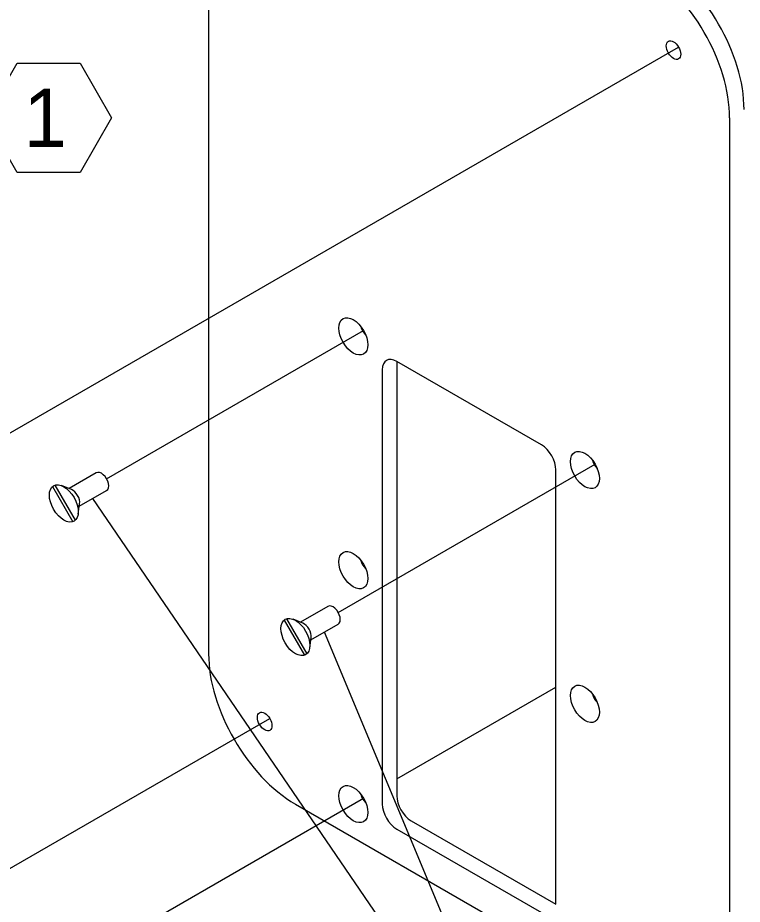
# Model space of a CAD drawing. Extents: x 99862 to 103151, y 100000 to 105076.
# Drawn here: x 100958 to 101157.1, y 103460 to 103703.7 of the extents above; entities that cross this region are included whole.
import ezdxf

# ---------------------------------------------------------------- set-up
doc = ezdxf.new("R2010")
doc.units = 0
for name, color, linetype in [('Level 15', 7, 'Continuous'), ('Level 16', 7, 'Continuous'), ('Level 20', 7, 'Continuous'), ('Level 41', 7, 'Continuous')]:
    doc.layers.add(name, color=color, linetype=linetype)

msp = doc.modelspace()

# ---------------------------------------------------------------- linework, layer by layer
at = {"layer": 'Level 15'}
for q in [(100978.65, 103571.56), (101042.29, 103534.82)]:
    msp.add_line((101102.82, 103389.59), q, dxfattribs=at)
at = {"layer": 'Level 16'}
for p, q in [((100947.75, 103584.89), (101139.59, 103695.65)), ((100982.4, 103576.97), (101053.01, 103617.74)), ((101046.04, 103540.23), (101116.65, 103581)), ((101062.13, 103494.41), (101105.88, 103519.67)), ((100954.54, 103469.03), (101027.26, 103511.02)), ((100982.4, 103448.37), (101053.01, 103489.14))]:
    msp.add_line(p, q, dxfattribs=at)
at = {"layer": 'Level 20'}
msp.add_lwpolyline([(100949.16, 103676.21), (100957.82, 103691.21), (100975.14, 103691.21), (100983.78, 103676.21), (100975.14, 103661.22), (100957.82, 103661.22), (100949.16, 103676.21)], dxfattribs=at)
at = {"layer": 'Level 41'}
for p, q in [((101010.42, 103758.86), (101010.42, 103528.85)), ((101153.61, 103676.19), (101153.61, 103446.18)), ((101062.13, 103609.23), (101062.13, 103489.81)), ((101101.9, 103586.26), (101062.13, 103609.23)), ((101058.15, 103606.93), (101058.15, 103487.52)), ((101105.88, 103459.96), (101105.88, 103579.37)), ((100979.58, 103578.59), (100972.09, 103574.27)), ((100967.53, 103574.84), (100973.12, 103565.16)), ((100968.18, 103575.21), (100973.77, 103565.54)), ((100972.73, 103574.01), (100970.03, 103575.08)), ((100974.9, 103569.39), (100982.4, 103573.72)), ((100974.58, 103567.21), (100975, 103570.08)), ((101043.22, 103541.85), (101035.73, 103537.52)), ((101031.17, 103538.1), (101036.76, 103528.42)), ((101031.82, 103538.47), (101037.41, 103528.79)), ((101036.37, 103537.27), (101033.67, 103538.34)), ((101038.54, 103532.65), (101046.04, 103536.98)), ((101038.22, 103530.47), (101038.64, 103533.33)), ((101034.29, 103487.52), (101129.75, 103432.4)), ((101066.11, 103482.93), (101105.88, 103459.96)), ((101062.13, 103480.63), (101101.9, 103457.66))]:
    msp.add_line(p, q, dxfattribs=at)
for centre, major_axis, start_param, end_param in [((101133.72, 103692.26), (-16.88, 29.23), 3.926991, 5.497787), ((101129.75, 103689.97), (-16.88, 29.23), 3.926991, 5.497787), ((101054.17, 103618.41), (-1.41, 2.44), 1.084101, 2.057491), ((101062.13, 103604.63), (-2.81, 4.87), 5.497787, 7.068583), ((101101.9, 103581.67), (-2.81, 4.87), 3.926991, 5.497787), ((101117.81, 103581.67), (-1.41, 2.44), 1.084101, 2.057491), ((100980.99, 103576.16), (1.41, -2.44), 6.28318, 9.424778), ((100980.99, 103576.16), (1.41, -2.44), 3.141593, 3.141605), ((100973.03, 103571.57), (1.41, -2.44), 0.630137, 2.511455), ((101054.17, 103554.11), (-1.41, 2.44), 1.084101, 2.057491), ((101044.63, 103539.42), (1.41, -2.44), 6.28318, 9.424778), ((101044.63, 103539.42), (1.41, -2.44), 3.141593, 3.141605), ((101036.67, 103534.82), (1.41, -2.44), 0.630137, 2.511453), ((101034.29, 103515.07), (16.88, -29.23), 3.926991, 5.497787), ((101117.81, 103517.37), (-1.41, 2.44), 1.084101, 2.057491), ((101054.17, 103489.81), (-1.41, 2.44), 1.084101, 2.057491), ((101066.11, 103487.52), (-2.81, 4.87), 0.785398, 2.356194), ((101062.13, 103485.22), (-2.81, 4.87), 0.785398, 2.356194)]:
    msp.add_ellipse(centre, major_axis=major_axis, ratio=0.57735, start_param=start_param, end_param=end_param, dxfattribs=at)
for centre, major_axis in [((101138.18, 103694.84), (-1.41, 2.44)), ((101050.2, 103616.12), (-2.81, 4.87)), ((101113.84, 103579.37), (-2.81, 4.87)), ((100970.65, 103570.19), (-2.81, 4.87)), ((101050.2, 103551.82), (-2.81, 4.87)), ((101034.29, 103533.45), (-2.81, 4.87)), ((101113.84, 103515.07), (-2.81, 4.87)), ((101025.85, 103510.2), (-1.41, 2.44)), ((101050.2, 103487.52), (-2.81, 4.87))]:
    msp.add_ellipse(centre, major_axis=major_axis, ratio=0.57735, dxfattribs=at)

# ---------------------------------------------------------------- texts
at = {"layer": 'Level 20'}
msp.add_text('1', height=16, dxfattribs=at).set_placement((100959.6, 103668.21))

doc.saveas('drawing.dxf')
